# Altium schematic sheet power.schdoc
size 400 x 277 mm; Device: default420x297; Symbol: default420x297; Name: default420x297; Size: "User"; Id: /; File: power; Sheet: /
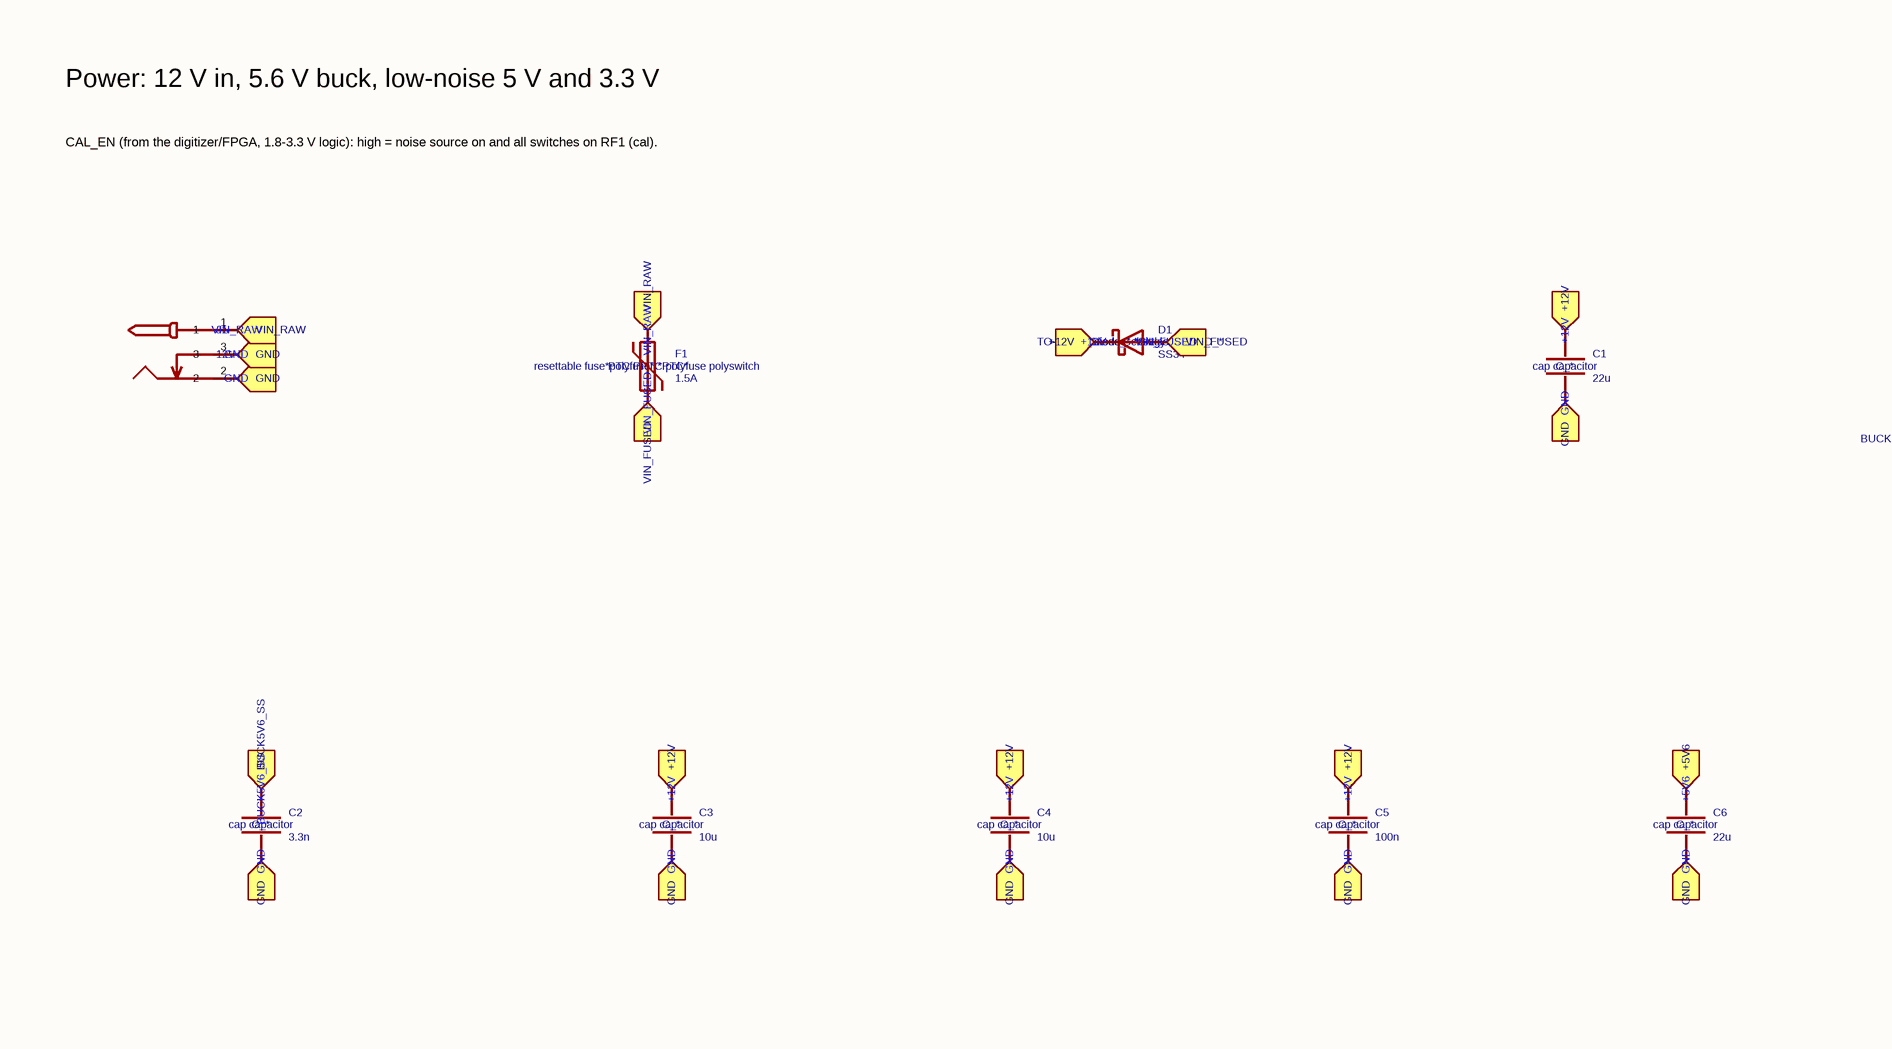
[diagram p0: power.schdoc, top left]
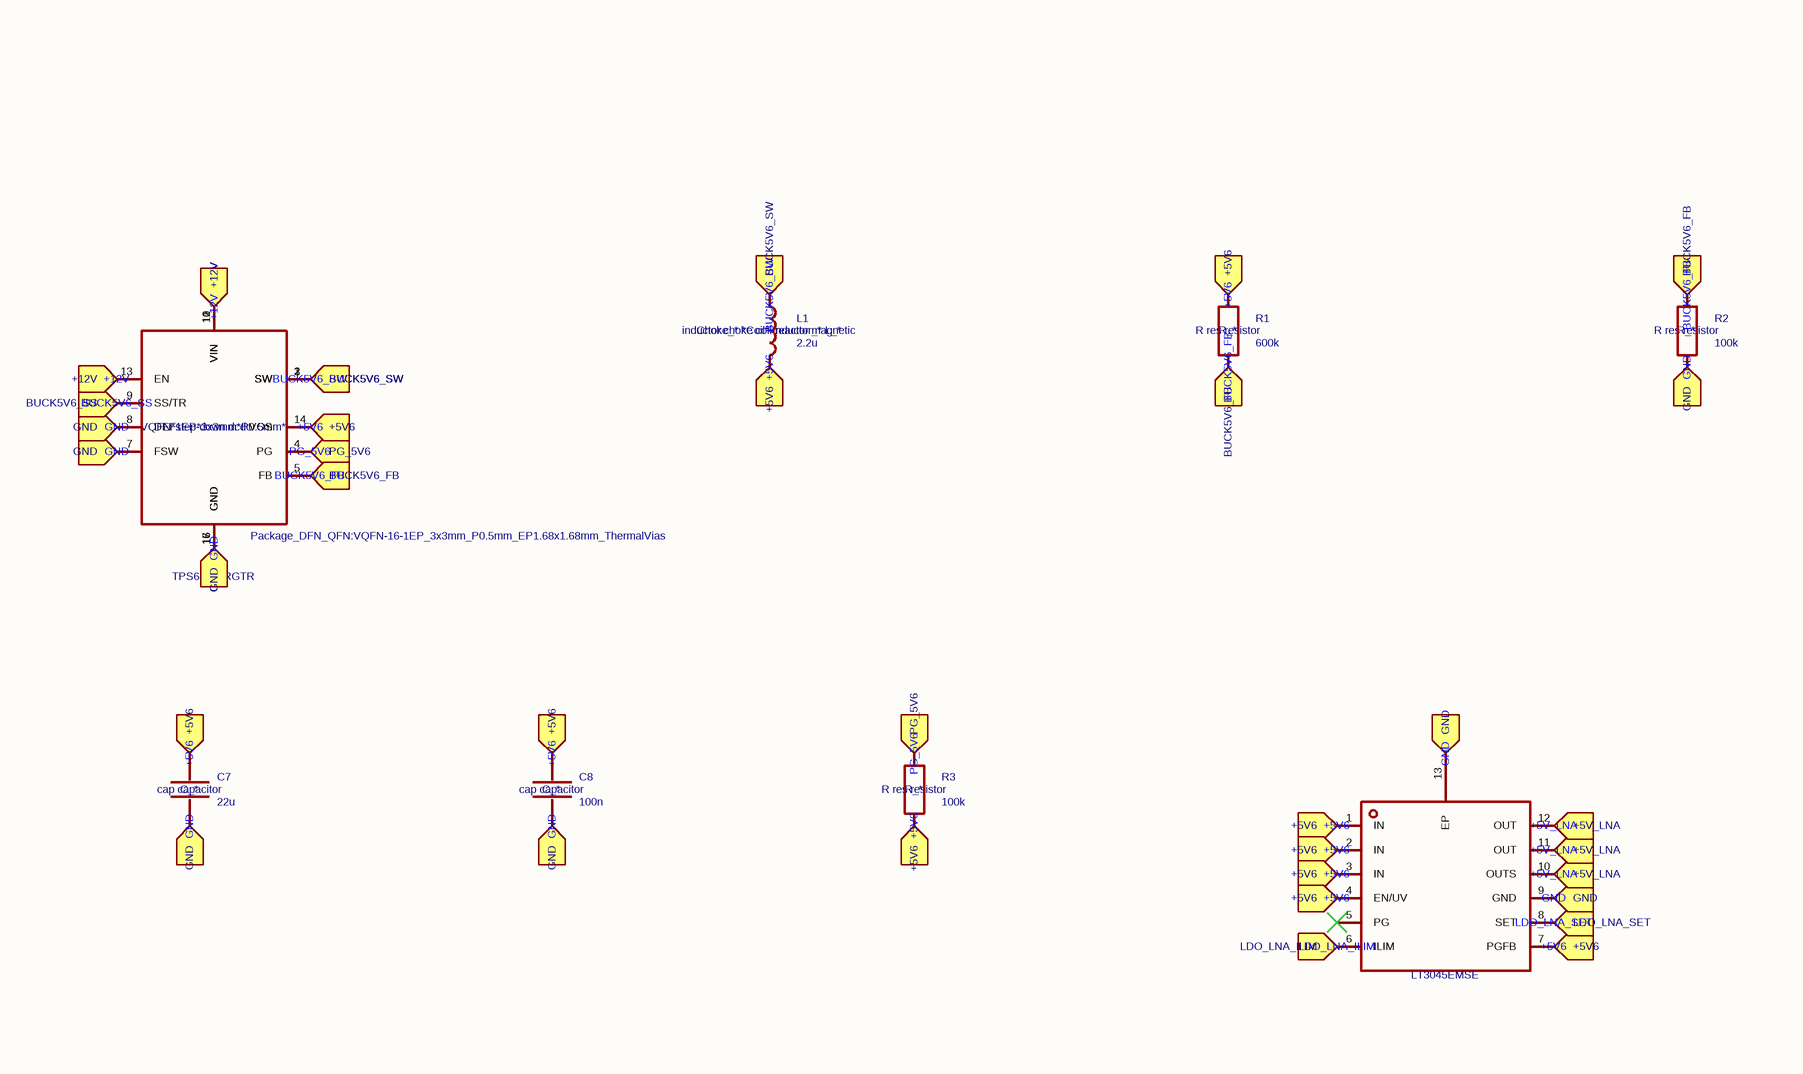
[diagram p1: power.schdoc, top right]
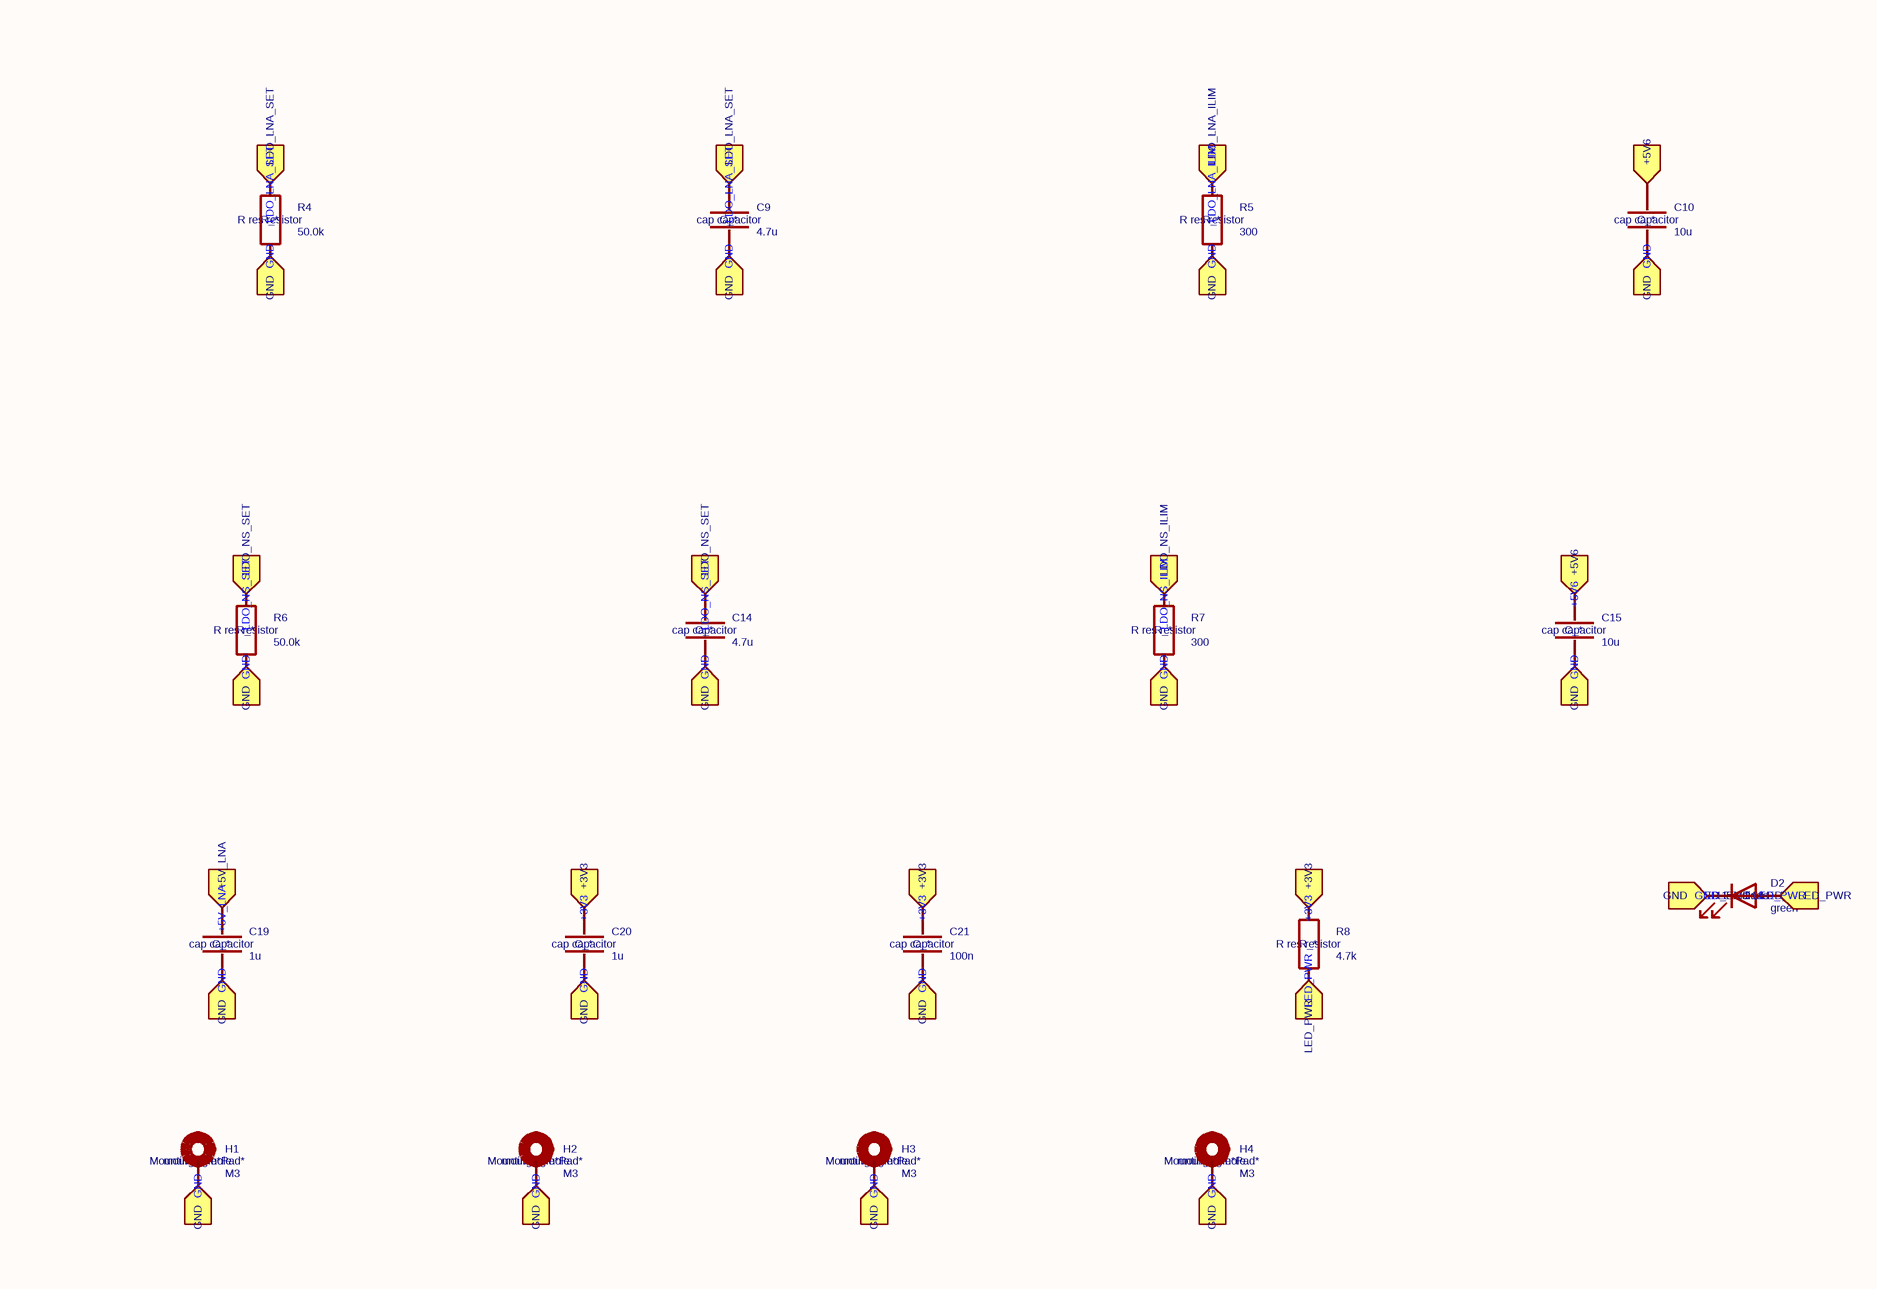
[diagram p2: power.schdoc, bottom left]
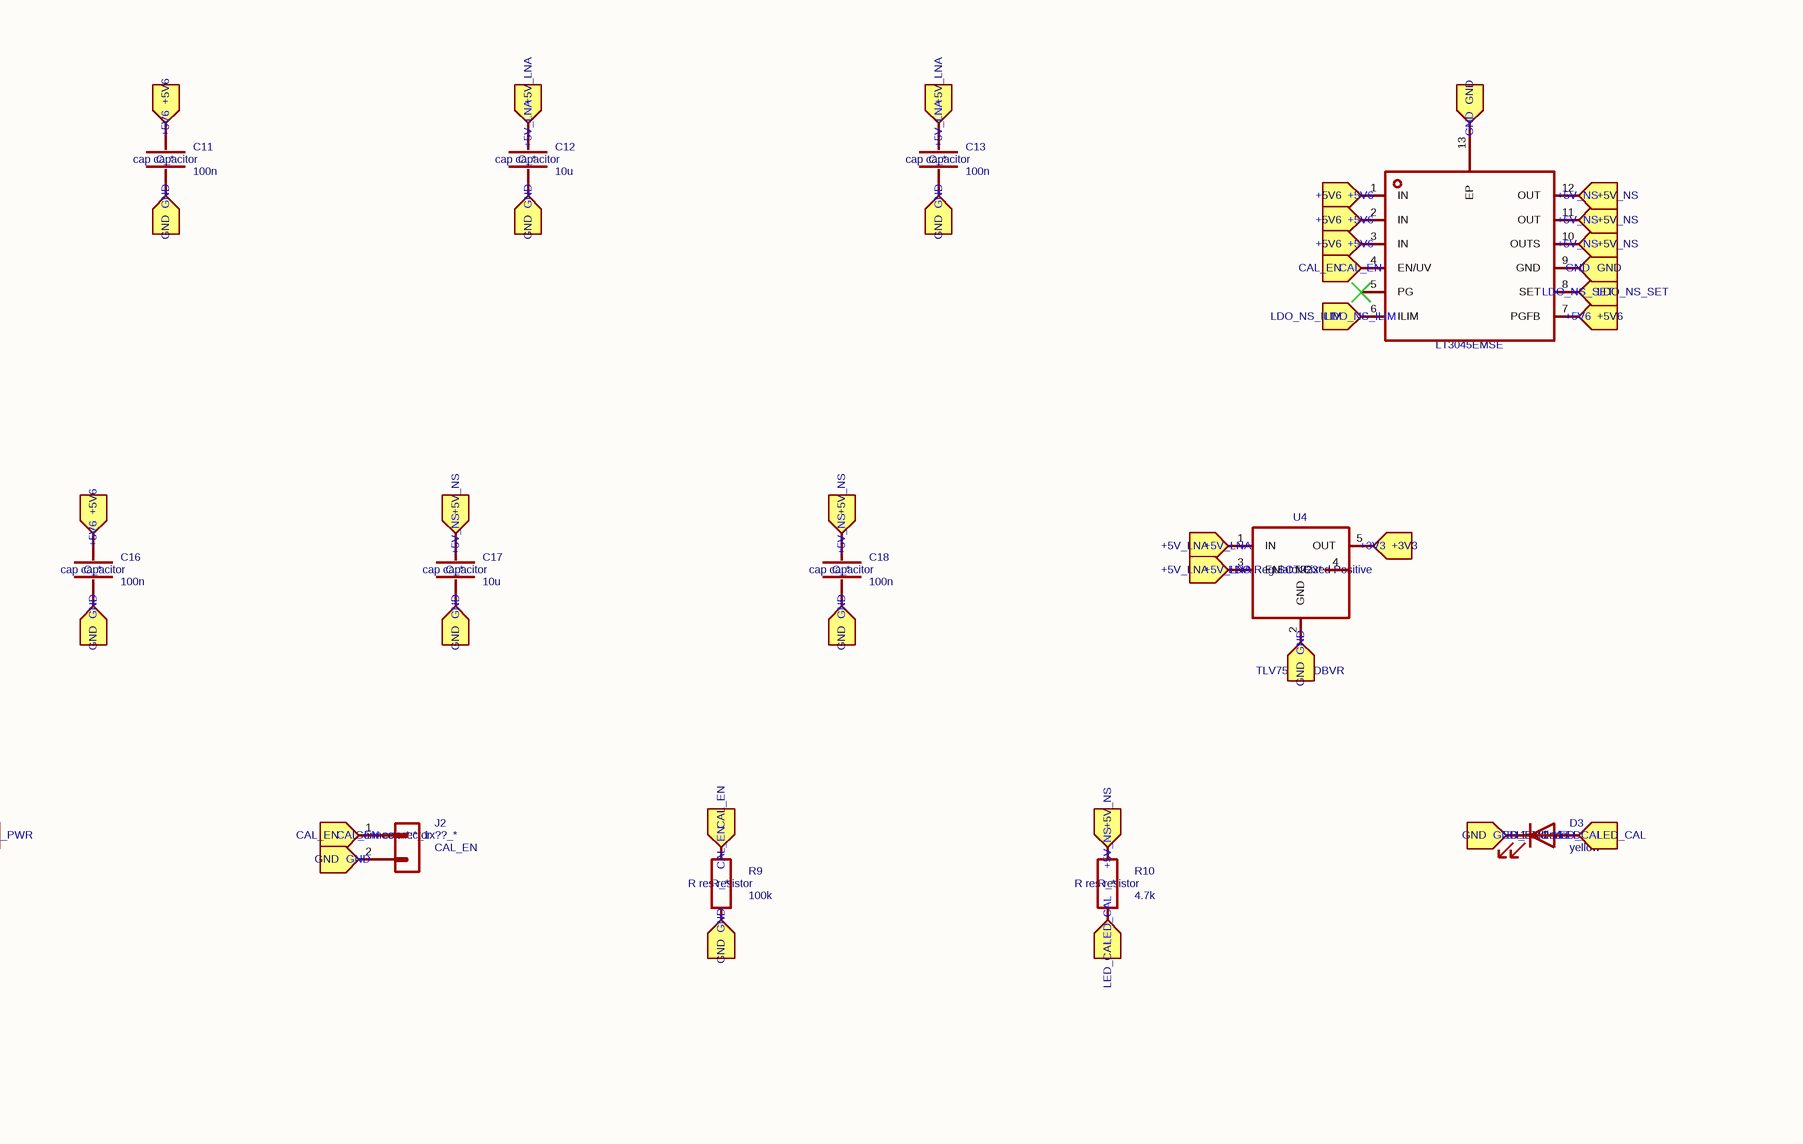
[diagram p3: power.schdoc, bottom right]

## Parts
C1  value 22u  ki_keywords: cap capacitor  ki_fp_filters: C_*  [Capacitor_SMD:C_1206_3216Metric]  (hidden comment: Device_C)
C2  value 3.3n  ki_keywords: cap capacitor  ki_fp_filters: C_*  [Capacitor_SMD:C_0402_1005Metric]  (hidden comment: Device_C)
C3  value 10u  ki_keywords: cap capacitor  ki_fp_filters: C_*  [Capacitor_SMD:C_0805_2012Metric]  (hidden comment: Device_C)
C4  value 10u  ki_keywords: cap capacitor  ki_fp_filters: C_*  [Capacitor_SMD:C_0805_2012Metric]  (hidden comment: Device_C)
C5  value 100n  ki_keywords: cap capacitor  ki_fp_filters: C_*  [Capacitor_SMD:C_0402_1005Metric]  (hidden comment: Device_C)
C6  value 22u  ki_keywords: cap capacitor  ki_fp_filters: C_*  [Capacitor_SMD:C_0805_2012Metric]  (hidden comment: Device_C)
C7  value 22u  ki_keywords: cap capacitor  ki_fp_filters: C_*  [Capacitor_SMD:C_0805_2012Metric]  (hidden comment: Device_C)
C8  value 100n  ki_keywords: cap capacitor  ki_fp_filters: C_*  [Capacitor_SMD:C_0402_1005Metric]  (hidden comment: Device_C)
C9  value 4.7u  ki_keywords: cap capacitor  ki_fp_filters: C_*  [Capacitor_SMD:C_0603_1608Metric]  (hidden comment: Device_C)
C10  value 10u  ki_keywords: cap capacitor  ki_fp_filters: C_*  [Capacitor_SMD:C_0603_1608Metric]  (hidden comment: Device_C)
C11  value 100n  ki_keywords: cap capacitor  ki_fp_filters: C_*  [Capacitor_SMD:C_0402_1005Metric]  (hidden comment: Device_C)
C12  value 10u  ki_keywords: cap capacitor  ki_fp_filters: C_*  [Capacitor_SMD:C_0603_1608Metric]  (hidden comment: Device_C)
C13  value 100n  ki_keywords: cap capacitor  ki_fp_filters: C_*  [Capacitor_SMD:C_0402_1005Metric]  (hidden comment: Device_C)
C14  value 4.7u  ki_keywords: cap capacitor  ki_fp_filters: C_*  [Capacitor_SMD:C_0603_1608Metric]  (hidden comment: Device_C)
C15  value 10u  ki_keywords: cap capacitor  ki_fp_filters: C_*  [Capacitor_SMD:C_0603_1608Metric]  (hidden comment: Device_C)
C16  value 100n  ki_keywords: cap capacitor  ki_fp_filters: C_*  [Capacitor_SMD:C_0402_1005Metric]  (hidden comment: Device_C)
C17  value 10u  ki_keywords: cap capacitor  ki_fp_filters: C_*  [Capacitor_SMD:C_0603_1608Metric]  (hidden comment: Device_C)
C18  value 100n  ki_keywords: cap capacitor  ki_fp_filters: C_*  [Capacitor_SMD:C_0402_1005Metric]  (hidden comment: Device_C)
C19  value 1u  ki_keywords: cap capacitor  ki_fp_filters: C_*  [Capacitor_SMD:C_0402_1005Metric]  (hidden comment: Device_C)
C20  value 1u  ki_keywords: cap capacitor  ki_fp_filters: C_*  [Capacitor_SMD:C_0402_1005Metric]  (hidden comment: Device_C)
C21  value 100n  ki_keywords: cap capacitor  ki_fp_filters: C_*  [Capacitor_SMD:C_0402_1005Metric]  (hidden comment: Device_C)
D1  value SS34  ki_keywords: diode Schottky  ki_fp_filters: TO-???* *_Diode_* *SingleDiode* D_*  [Diode_SMD:D_SMA]  (hidden comment: Device_D_Schottky)
D2  value green  Sim.Pins: 1=K 2=A  ki_keywords: LED diode  ki_fp_filters: LED* LED_SMD:* LED_THT:*  [LED_SMD:LED_0603_1608Metric]  (hidden comment: Device_LED)
D3  value yellow  Sim.Pins: 1=K 2=A  ki_keywords: LED diode  ki_fp_filters: LED* LED_SMD:* LED_THT:*  [LED_SMD:LED_0603_1608Metric]  (hidden comment: Device_LED)
F1  value 1.5A  ki_keywords: resettable fuse PTC PPTC polyfuse polyswitch  ki_fp_filters: *polyfuse* *PTC*  [Fuse:Fuse_1206_3216Metric]  (hidden comment: Device_Polyfuse)
H1  value M3  ki_keywords: mounting hole  ki_fp_filters: MountingHole*Pad*  [MountingHole:MountingHole_3.2mm_M3_Pad_Via]  (hidden comment: Mechanical_MountingHole_Pad)
H2  value M3  ki_keywords: mounting hole  ki_fp_filters: MountingHole*Pad*  [MountingHole:MountingHole_3.2mm_M3_Pad_Via]  (hidden comment: Mechanical_MountingHole_Pad)
H3  value M3  ki_keywords: mounting hole  ki_fp_filters: MountingHole*Pad*  [MountingHole:MountingHole_3.2mm_M3_Pad_Via]  (hidden comment: Mechanical_MountingHole_Pad)
H4  value M3  ki_keywords: mounting hole  ki_fp_filters: MountingHole*Pad*  [MountingHole:MountingHole_3.2mm_M3_Pad_Via]  (hidden comment: Mechanical_MountingHole_Pad)
J1  value 12V DC  [prc:DC-IN-TH_DC-005C-20A]  (hidden comment: prc_DC-005C-20A)
J2  value CAL_EN  ki_keywords: connector  ki_fp_filters: Connector*:*_1x??_*  [Connector_PinHeader_2.54mm:PinHeader_1x02_P2.54mm_Vertical]  (hidden comment: Connector_Generic_Conn_01x02)
L1  value 2.2u  ki_keywords: inductor choke coil reactor magnetic  ki_fp_filters: Choke_* *Coil* Inductor_* L_*  [Inductor_SMD:L_Bourns-SRN4018]  (hidden comment: Device_L)
R1  value 600k  ki_keywords: R res resistor  ki_fp_filters: R_*  [Resistor_SMD:R_0402_1005Metric]  (hidden comment: Device_R)
R2  value 100k  ki_keywords: R res resistor  ki_fp_filters: R_*  [Resistor_SMD:R_0402_1005Metric]  (hidden comment: Device_R)
R3  value 100k  ki_keywords: R res resistor  ki_fp_filters: R_*  [Resistor_SMD:R_0402_1005Metric]  (hidden comment: Device_R)
R4  value 50.0k  ki_keywords: R res resistor  ki_fp_filters: R_*  [Resistor_SMD:R_0402_1005Metric]  (hidden comment: Device_R)
R5  value 300  ki_keywords: R res resistor  ki_fp_filters: R_*  [Resistor_SMD:R_0402_1005Metric]  (hidden comment: Device_R)
R6  value 50.0k  ki_keywords: R res resistor  ki_fp_filters: R_*  [Resistor_SMD:R_0402_1005Metric]  (hidden comment: Device_R)
R7  value 300  ki_keywords: R res resistor  ki_fp_filters: R_*  [Resistor_SMD:R_0402_1005Metric]  (hidden comment: Device_R)
R8  value 4.7k  ki_keywords: R res resistor  ki_fp_filters: R_*  [Resistor_SMD:R_0402_1005Metric]  (hidden comment: Device_R)
R9  value 100k  ki_keywords: R res resistor  ki_fp_filters: R_*  [Resistor_SMD:R_0402_1005Metric]  (hidden comment: Device_R)
R10  value 4.7k  ki_keywords: R res resistor  ki_fp_filters: R_*  [Resistor_SMD:R_0402_1005Metric]  (hidden comment: Device_R)
U1  value TPS62130RGTR  ki_keywords: step-down dcdc  ki_fp_filters: VQFN*1EP*3x3mm*P0.5mm*  Origin Footprint: Package_DFN_QFN:VQFN-16-1EP_3x3mm_P0.5mm_EP1.68x1.68mm_ThermalVias  [Package_DFN_QFN:VQFN-16-1EP_3x3mm_P0.5mm_EP1.68x1.68mm]  (hidden comment: Regulator_Switching_TPS62130)
U2  value LT3045EMSE  [prc:MSOP-12_L4.0-W3.0-P0.65-LS4.9-BL-EP]  (hidden comment: prc_LT3045EMSE#PBF)
U3  value LT3045EMSE  [prc:MSOP-12_L4.0-W3.0-P0.65-LS4.9-BL-EP]  (hidden comment: prc_LT3045EMSE#PBF)
U4  value TLV75533PDBVR  ki_keywords: LDO Regulator Fixed Positive  ki_fp_filters: SOT?23*  [Package_TO_SOT_SMD:SOT-23-5]  (hidden comment: Regulator_Linear_TLV75533PDBV)

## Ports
+3V3 (in), +5V6 (in), +5V_LNA (in), +5V_NS (in), +12V (in), BUCK5V6_FB (in), BUCK5V6_SS (in), BUCK5V6_SW (in), CAL_EN (in), GND (in), LDO_LNA_ILIM (in), LDO_LNA_SET (in), LDO_NS_ILIM (in), LDO_NS_SET (in), LED_CAL (in), LED_PWR (in), PG_5V6 (in), VIN_FUSED (in), VIN_RAW (in)

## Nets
+3V3: C20.1 C21.1 R8.1 U4.5(OUT) ; port +3V3
+5V6: C6.1 C7.1 C8.1 C10.1 C11.1 C15.1 C16.1 L1.2 R1.1 R3.2 U1.14(VOS) U2.1(IN) U2.2(IN) U2.3(IN) U2.4(EN/UV) U2.7(PGFB) U3.1(IN) U3.2(IN) U3.3(IN) U3.7(PGFB) ; port +5V6
+5V_LNA: C12.1 C13.1 C19.1 U2.10(OUTS) U2.11(OUT) U2.12(OUT) U4.1(IN) U4.3(EN) ; port +5V_LNA
+5V_NS: C17.1 C18.1 R10.1 U3.10(OUTS) U3.11(OUT) U3.12(OUT) ; port +5V_NS
+12V: C1.1 C3.1 C4.1 C5.1 D1.1(K) U1.10(VIN) U1.11(VIN) U1.12(VIN) U1.13(EN) ; port +12V
BUCK5V6_FB: R1.2 R2.1 U1.5(FB) ; port BUCK5V6_FB
BUCK5V6_SS: C2.1 U1.9(SS/TR) ; port BUCK5V6_SS
BUCK5V6_SW: L1.1 U1.1(SW) U1.2(SW) U1.3(SW) ; port BUCK5V6_SW
CAL_EN: J2.1(Pin_1) R9.1 U3.4(EN/UV) ; port CAL_EN
GND: C1.2 C2.2 C3.2 C4.2 C5.2 C6.2 C7.2 C8.2 C9.2 C10.2 C11.2 C12.2 C13.2 C14.2 C15.2 C16.2 C17.2 C18.2 C19.2 C20.2 C21.2 D2.1(K) D3.1(K) H1.1 H2.1 H3.1 H4.1 J1.2 J1.3 J2.2(Pin_2) R2.2 R4.2 R5.2 R6.2 R7.2 R9.2 U1.6(GND) U1.7(FSW) U1.8(DEF) U1.15(GND) U1.16(GND) U1.17(GND) U2.9(GND) U2.13(EP) U3.9(GND) U3.13(EP) U4.2(GND) ; port GND
LDO_LNA_ILIM: R5.1 U2.6(ILIM) ; port LDO_LNA_ILIM
LDO_LNA_SET: C9.1 R4.1 U2.8(SET) ; port LDO_LNA_SET
LDO_NS_ILIM: R7.1 U3.6(ILIM) ; port LDO_NS_ILIM
LDO_NS_SET: C14.1 R6.1 U3.8(SET) ; port LDO_NS_SET
LED_CAL: D3.2(A) R10.2 ; port LED_CAL
LED_PWR: D2.2(A) R8.2 ; port LED_PWR
PG_5V6: R3.1 U1.4(PG) ; port PG_5V6
VIN_FUSED: D1.2(A) F1.2 ; port VIN_FUSED
VIN_RAW: F1.1 J1.1 ; port VIN_RAW

Not connected (* = marked no-connect by the designer): U2 5(PG)*; U3 5(PG)*; U4 4(NC)

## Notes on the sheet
- Power: 12 V in, 5.6 V buck, low-noise 5 V and 3.3 V
- CAL_EN (from the digitizer/FPGA, 1.8-3.3 V logic): high = noise source on and all switches on RF1 (cal).

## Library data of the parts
C1 = Device_C: UniqueId: b4693cfd16d534cd; KiLib_Generator: SMD_2terminal_chip_molded; AddInBom: yes
C2 = Device_C: UniqueId: a2c5d49bc5dde298; KiLib_Generator: SMD_2terminal_chip_molded; AddInBom: yes
C3 = Device_C: UniqueId: cc82bf2c2e22e605; KiLib_Generator: SMD_2terminal_chip_molded; AddInBom: yes
C4 = Device_C: UniqueId: 3a68d3ddabf48558; KiLib_Generator: SMD_2terminal_chip_molded; AddInBom: yes
C5 = Device_C: UniqueId: ddba3c46cf8b8e66; KiLib_Generator: SMD_2terminal_chip_molded; AddInBom: yes
C6 = Device_C: UniqueId: ab4a8fe24fad9fe4; KiLib_Generator: SMD_2terminal_chip_molded; AddInBom: yes
C7 = Device_C: UniqueId: 48d2dd422533522c; KiLib_Generator: SMD_2terminal_chip_molded; AddInBom: yes
C8 = Device_C: UniqueId: 80f3708378e3d903; KiLib_Generator: SMD_2terminal_chip_molded; AddInBom: yes
C9 = Device_C: UniqueId: 7ddfd2f632a8b17d; KiLib_Generator: SMD_2terminal_chip_molded; AddInBom: yes
C10 = Device_C: UniqueId: 3e75135af30e0f04; KiLib_Generator: SMD_2terminal_chip_molded; AddInBom: yes
C11 = Device_C: UniqueId: 20764de07767b3a1; KiLib_Generator: SMD_2terminal_chip_molded; AddInBom: yes
C12 = Device_C: UniqueId: 26a39bcafcc8ce7c; KiLib_Generator: SMD_2terminal_chip_molded; AddInBom: yes
C13 = Device_C: UniqueId: e7ba3aba9f9889c8; KiLib_Generator: SMD_2terminal_chip_molded; AddInBom: yes
C14 = Device_C: UniqueId: 00361082df9d4549; KiLib_Generator: SMD_2terminal_chip_molded; AddInBom: yes
C15 = Device_C: UniqueId: 86bb77bda672094d; KiLib_Generator: SMD_2terminal_chip_molded; AddInBom: yes
C16 = Device_C: UniqueId: c8e923f96b539988; KiLib_Generator: SMD_2terminal_chip_molded; AddInBom: yes
C17 = Device_C: UniqueId: 48700c84863a802e; KiLib_Generator: SMD_2terminal_chip_molded; AddInBom: yes
C18 = Device_C: UniqueId: d9d0285421fe3ef0; KiLib_Generator: SMD_2terminal_chip_molded; AddInBom: yes
C19 = Device_C: UniqueId: 9b75bd895f0e39d2; KiLib_Generator: SMD_2terminal_chip_molded; AddInBom: yes
C20 = Device_C: UniqueId: 97d7532320e593d5; KiLib_Generator: SMD_2terminal_chip_molded; AddInBom: yes
C21 = Device_C: UniqueId: 0259cc883dd91c7a; KiLib_Generator: SMD_2terminal_chip_molded; AddInBom: yes
D1 = Device_D_Schottky: UniqueId: 6eb2f7ba7a12821c; AddInBom: yes
D2 = Device_LED: UniqueId: cca08e5caf06c018; KiLib_Generator: SMD_2terminal_chip_molded; AddInBom: yes
D3 = Device_LED: UniqueId: 81689f1d3303caec; KiLib_Generator: SMD_2terminal_chip_molded; AddInBom: yes
F1 = Device_Polyfuse: UniqueId: 09f31a4987c8a883; KiLib_Generator: SMD_2terminal_chip_molded; AddInBom: yes
H1 = Mechanical_MountingHole_Pad: UniqueId: 42baa21c67f8a3af; KiLib_Generator: mounting_hardware/mounting_hole; AddInBom: yes
H2 = Mechanical_MountingHole_Pad: UniqueId: b7e18a508253e952; KiLib_Generator: mounting_hardware/mounting_hole; AddInBom: yes
H3 = Mechanical_MountingHole_Pad: UniqueId: 0c3ab7284e9cbe73; KiLib_Generator: mounting_hardware/mounting_hole; AddInBom: yes
H4 = Mechanical_MountingHole_Pad: UniqueId: a89bd88a2d6d819d; KiLib_Generator: mounting_hardware/mounting_hole; AddInBom: yes
J1 = prc_DC-005C-20A: Manufacturer: 韩国韩荣; ki_keywords: AC/DC Power Connectors; ki_description: DC-005 2.0mm; UniqueId: 51bfc0e5166a1c40; AddInBom: yes
J2 = Connector_Generic_Conn_01x02: UniqueId: 1fb9863844ab5169; KiLib_Generator: connector/pin_header_socket; AddInBom: yes
L1 = Device_L: MPN: SRN4018-2R2M; UniqueId: d450ceac7adb81c3; AddInBom: yes
R1 = Device_R: UniqueId: 353b166cc2dee846; KiLib_Generator: SMD_2terminal_chip_molded; AddInBom: yes
R2 = Device_R: UniqueId: 6f63fc6711cfa315; KiLib_Generator: SMD_2terminal_chip_molded; AddInBom: yes
R3 = Device_R: UniqueId: fe89d0632cfce75f; KiLib_Generator: SMD_2terminal_chip_molded; AddInBom: yes
R4 = Device_R: Tolerance: 0.1%; UniqueId: fdc86a4b576d9e98; KiLib_Generator: SMD_2terminal_chip_molded; AddInBom: yes
R5 = Device_R: UniqueId: 9cdd622c9eeecfe7; KiLib_Generator: SMD_2terminal_chip_molded; AddInBom: yes
R6 = Device_R: Tolerance: 0.1%; UniqueId: e06ccd13940482ac; KiLib_Generator: SMD_2terminal_chip_molded; AddInBom: yes
R7 = Device_R: UniqueId: ba2c6d155e7fd301; KiLib_Generator: SMD_2terminal_chip_molded; AddInBom: yes
R8 = Device_R: UniqueId: 86d447fa2a9c8586; KiLib_Generator: SMD_2terminal_chip_molded; AddInBom: yes
R9 = Device_R: UniqueId: 1e1ffada38203b9e; KiLib_Generator: SMD_2terminal_chip_molded; AddInBom: yes
R10 = Device_R: UniqueId: 41bc0941336b1513; KiLib_Generator: SMD_2terminal_chip_molded; AddInBom: yes
U1 = Regulator_Switching_TPS62130: UniqueId: 1bdc0ab44f99f92d; KiLib_Generator: package/no_lead; AddInBom: yes
U2 = prc_LT3045EMSE#PBF: Manufacturer: ADI(亚德诺); ki_keywords: Linear Voltage Regulators (LDO); UniqueId: 48f0ae2437312dae; AddInBom: yes
U3 = prc_LT3045EMSE#PBF: Manufacturer: ADI(亚德诺); ki_keywords: Linear Voltage Regulators (LDO); UniqueId: 66797bcd97f4f6c2; AddInBom: yes
U4 = Regulator_Linear_TLV75533PDBV: UniqueId: bac468049775df37; KiLib_Generator: package/gullwing; AddInBom: yes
